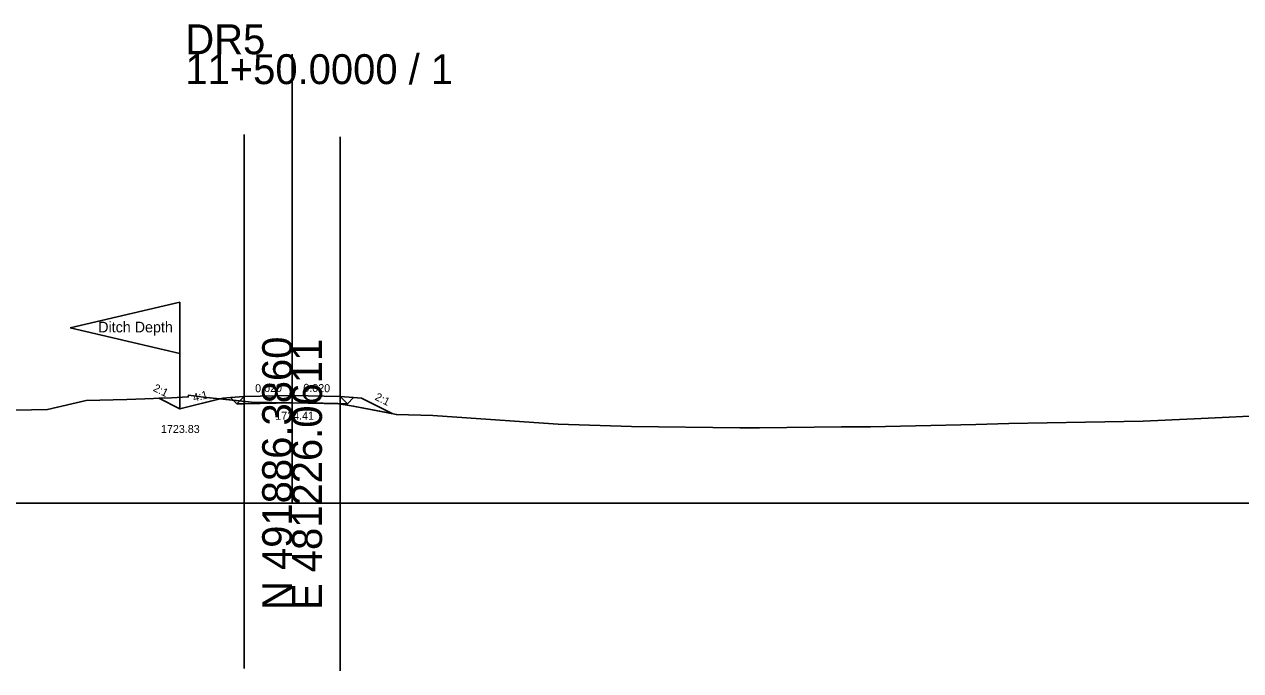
# Model space of a CAD drawing. Extents: x -26 to 403, y -10 to 2534.
# Drawn here: x 174.9 to 288.9, y 1484.3 to 1544.8 of the extents above; entities that cross this region are included whole.
import ezdxf

# ---------------------------------------------------------------- set-up
doc = ezdxf.new("R2010")
doc.units = 0
for name, color, linetype in [('Exist Cross Section Cell', 7, 'Continuous'), ('Exist XS Center Line Elevation Label', 7, 'Continuous'), ('Exist XS Ground Line', 7, 'Continuous'), ('Prop Road Sect_ Boring - Material (Outline)', 7, 'Continuous'), ('Prop XS Ditch Slope Text', 7, 'Continuous'), ('Prop XS Ditch Standard Text', 7, 'Continuous'), ('Prop XS Dump Level', 7, 'Continuous'), ('Prop XS Earthwork Shape', 7, 'Continuous'), ('Prop XS EOT Tick Mark', 7, 'Continuous'), ('Prop XS Finish Grade', 7, 'Continuous'), ('Prop XS Finish Grade Earthwork', 7, 'Continuous'), ('Prop XS Finish Grade Pavement', 7, 'Continuous'), ('Prop XS Hydro Typical Ditch Data', 7, 'Continuous'), ('Prop XS Pvmt Edge Slope', 7, 'Continuous'), ('Prop XS SE Text', 7, 'Continuous'), ('Prop XS Side Slope Text', 7, 'Continuous'), ('Prop XS Subgrade Earthwork', 7, 'Continuous'), ('Scratch_Level_4', 7, 'Continuous'), ('Scratch_Level_5', 7, 'Continuous')]:
    doc.layers.add(name, color=color, linetype=linetype)

msp = doc.modelspace()

# ---------------------------------------------------------------- linework, layer by layer
at = {"layer": 'Exist Cross Section Cell'}
for p, q in [((200, 1500), (200, 1542.05)), ((0, 1500), (200, 1500)), ((200, 1500), (400, 1500))]:
    msp.add_line(p, q, dxfattribs=at)
at = {"layer": 'Exist XS Ground Line'}
msp.add_lwpolyline([(174.1, 1508.73), (177.08, 1508.77), (180.72, 1509.61), (184.52, 1509.73), (188.7, 1509.86), (190.28, 1509.96), (190.29, 1510.11), (191.71, 1509.92), (196.2, 1509.46), (200, 1509.41), (202.91, 1509.36), (204.18, 1509.35), (205.74, 1509.1), (209.77, 1508.31), (213.2, 1508.23), (223.56, 1507.49), (224.94, 1507.4), (231.81, 1507.18), (241.95, 1507.06), (243.78, 1507.07), (251.48, 1507.14), (253.77, 1507.17), (254.21, 1507.16), (264.07, 1507.37), (267.15, 1507.47), (274.33, 1507.59), (279.75, 1507.69), (284.51, 1507.89), (292.35, 1508.29)], dxfattribs=at)
at = {"layer": 'Prop Road Sect_ Boring - Material (Outline)'}
for points in [[(195.5, 1509.99), (194.82, 1509.31), (194.24, 1509.89)], [(205.18, 1509.31), (205.76, 1509.89), (204.5, 1509.99)]]:
    msp.add_lwpolyline(points, close=True, dxfattribs=at)
at = {"layer": 'Prop XS Dump Level'}
for p, q in [((189.5, 1518.83), (179.2, 1516.43)), ((189.5, 1514.03), (189.5, 1518.83)), ((179.2, 1516.43), (189.5, 1514.03)), ((189.5, 1508.83), (189.5, 1514.03)), ((200, 1510.08), (195.5, 1509.99)), ((204.5, 1509.99), (200, 1510.08))]:
    msp.add_line(p, q, dxfattribs=at)
at = {"layer": 'Prop XS Earthwork Shape'}
for points in [[(193.24, 1509.77), (189.5, 1508.83), (187.51, 1509.83), (188.7, 1509.86), (190.28, 1509.96), (190.29, 1510.11), (191.71, 1509.92)], [(193.24, 1509.77), (189.5, 1508.83), (187.51, 1509.83), (188.7, 1509.86), (190.28, 1509.96), (190.29, 1510.11), (191.71, 1509.92)], [(193.24, 1509.77), (189.5, 1508.83), (187.51, 1509.83), (188.7, 1509.86), (190.28, 1509.96), (190.29, 1510.11), (191.71, 1509.92)], [(193.24, 1509.77), (189.5, 1508.83), (187.51, 1509.83), (188.7, 1509.86), (190.28, 1509.96), (190.29, 1510.11), (191.71, 1509.92)], [(194.49, 1509.64), (194.24, 1509.89), (193.5, 1509.83), (193.24, 1509.77)], [(193.24, 1509.77), (194.49, 1509.64), (194.24, 1509.89), (193.5, 1509.83)], [(194.49, 1509.64), (194.24, 1509.89), (193.5, 1509.83), (193.24, 1509.77)], [(194.49, 1509.64), (194.24, 1509.89), (193.5, 1509.83), (193.24, 1509.77)], [(194.49, 1509.64), (196.2, 1509.46), (200, 1509.41), (195.5, 1509.32), (194.82, 1509.31)], [(194.49, 1509.64), (196.2, 1509.46), (200, 1509.41), (195.5, 1509.32), (194.82, 1509.31)], [(194.49, 1509.64), (196.2, 1509.46), (200, 1509.41), (195.5, 1509.32), (194.82, 1509.31)], [(194.49, 1509.64), (196.2, 1509.46), (200, 1509.41), (195.5, 1509.32), (194.82, 1509.31)], [(204.3, 1509.33), (200, 1509.41), (202.91, 1509.36), (204.18, 1509.35)], [(204.3, 1509.33), (200, 1509.41), (202.91, 1509.36), (204.18, 1509.35)], [(204.3, 1509.33), (200, 1509.41), (202.91, 1509.36), (204.18, 1509.35)], [(204.3, 1509.33), (200, 1509.41), (202.91, 1509.36), (204.18, 1509.35)], [(204.3, 1509.33), (205.74, 1509.1), (209.38, 1508.39), (206.5, 1509.83), (205.76, 1509.89), (205.18, 1509.31), (204.5, 1509.32)], [(204.3, 1509.33), (205.74, 1509.1), (209.38, 1508.39), (206.5, 1509.83), (205.76, 1509.89), (205.18, 1509.31), (204.5, 1509.32)], [(204.3, 1509.33), (205.74, 1509.1), (209.38, 1508.39), (206.5, 1509.83), (205.76, 1509.89), (205.18, 1509.31), (204.5, 1509.32)], [(204.3, 1509.33), (205.74, 1509.1), (209.38, 1508.39), (206.5, 1509.83), (205.76, 1509.89), (205.18, 1509.31), (204.5, 1509.32)]]:
    msp.add_lwpolyline(points, close=True, dxfattribs=at)
at = {"layer": 'Prop XS EOT Tick Mark'}
for p, q in [((195.5, 1509.99), (195.5, 1510.99)), ((204.5, 1509.99), (204.5, 1510.99))]:
    msp.add_line(p, q, dxfattribs=at)
at = {"layer": 'Prop XS Finish Grade'}
for p, q in [((195.5, 1509.99), (194.24, 1509.89)), ((204.5, 1509.99), (205.76, 1509.89))]:
    msp.add_line(p, q, dxfattribs=at)
at = {"layer": 'Prop XS Finish Grade Earthwork'}
for p, q in [((189.5, 1508.83), (187.51, 1509.83)), ((193.5, 1509.83), (189.5, 1508.83)), ((194.24, 1509.89), (193.5, 1509.83)), ((205.76, 1509.89), (206.5, 1509.83)), ((206.5, 1509.83), (209.38, 1508.39))]:
    msp.add_line(p, q, dxfattribs=at)
at = {"layer": 'Prop XS Finish Grade Pavement'}
for p, q in [((195.5, 1509.99), (200, 1510.08)), ((200, 1510.08), (204.5, 1509.99))]:
    msp.add_line(p, q, dxfattribs=at)
at = {"layer": 'Prop XS Hydro Typical Ditch Data'}
for p, q in [((189.5, 1508.83), (187.51, 1509.83)), ((193.5, 1509.83), (189.5, 1508.83))]:
    msp.add_line(p, q, dxfattribs=at)
at = {"layer": 'Prop XS Pvmt Edge Slope'}
for p, q in [((195.5, 1509.99), (194.82, 1509.31)), ((204.5, 1509.99), (205.18, 1509.31))]:
    msp.add_line(p, q, dxfattribs=at)
at = {"layer": 'Prop XS Subgrade Earthwork'}
for p, q in [((194.82, 1509.31), (194.24, 1509.89)), ((195.5, 1509.32), (194.82, 1509.31)), ((200, 1509.41), (195.5, 1509.32)), ((204.5, 1509.32), (200, 1509.41)), ((204.5, 1509.32), (205.18, 1509.31)), ((205.18, 1509.31), (205.76, 1509.89))]:
    msp.add_line(p, q, dxfattribs=at)
at = {"layer": 'Scratch_Level_4'}
for p, q in [((195.5, 1534.53), (195.5, 1484.53)), ((204.5, 1534.32), (204.5, 1484.32))]:
    msp.add_line(p, q, dxfattribs=at)
at = {"layer": 'Scratch_Level_5'}
msp.add_lwpolyline([(174.1, 1508.73), (177.08, 1508.77), (180.72, 1509.61), (184.52, 1509.73), (188.7, 1509.86), (190.28, 1509.96), (190.29, 1510.11), (191.71, 1509.92), (196.2, 1509.46), (200, 1509.41), (202.91, 1509.36), (204.18, 1509.35), (205.74, 1509.1), (209.77, 1508.31), (213.2, 1508.23), (223.56, 1507.49), (224.94, 1507.4), (231.81, 1507.18), (241.95, 1507.06), (243.78, 1507.07), (251.48, 1507.14), (253.77, 1507.17), (254.21, 1507.16), (264.07, 1507.37), (267.15, 1507.47), (274.33, 1507.59), (279.75, 1507.69), (284.51, 1507.89), (292.35, 1508.29)], dxfattribs=at)

# ---------------------------------------------------------------- texts
at = {"layer": 'Exist Cross Section Cell'}
for s, p in [('DR5', (190, 1542.05)), ('11+50.0000 / 1', (190, 1539.25))]:
    msp.add_text(s, height=2.8, dxfattribs=at).set_placement(p)
for s, p in [('N 491886.3860', (200, 1490)), ('E 481226.0611', (202.8, 1490))]:
    msp.add_text(s, height=2.8, rotation=90, dxfattribs=at).set_placement(p)
at = {"layer": 'Exist XS Center Line Elevation Label'}
msp.add_text('1724.41', height=0.75, dxfattribs=at).set_placement((198.43, 1507.82))
at = {"layer": 'Prop XS Ditch Slope Text'}
msp.add_text('4:1', height=0.75, rotation=14.0362, dxfattribs=at).set_placement((190.81, 1509.5))
at = {"layer": 'Prop XS Ditch Standard Text'}
msp.add_text('1723.83', height=0.75, dxfattribs=at).set_placement((187.72, 1506.58))
at = {"layer": 'Prop XS Dump Level'}
for s, height, p in [('Ditch Depth', 1, (181.84, 1516)), ('Case1', 0.04, (193.5, 1509.79)), ('Case1', 0.04, (206.5, 1509.79))]:
    msp.add_text(s, height=height, dxfattribs=at).set_placement(p)
at = {"layer": 'Prop XS SE Text'}
for rotation, p in [(1.1458, (196.55, 1510.39)), (358.8542, (201.05, 1510.44))]:
    msp.add_text('0.020', height=0.75, rotation=rotation, dxfattribs=at).set_placement(p)
at = {"layer": 'Prop XS Side Slope Text'}
for p in [(186.92, 1510.55), (207.69, 1509.72)]:
    msp.add_text('2:1', height=0.75, rotation=333.4349, dxfattribs=at).set_placement(p)

doc.saveas('drawing.dxf')
